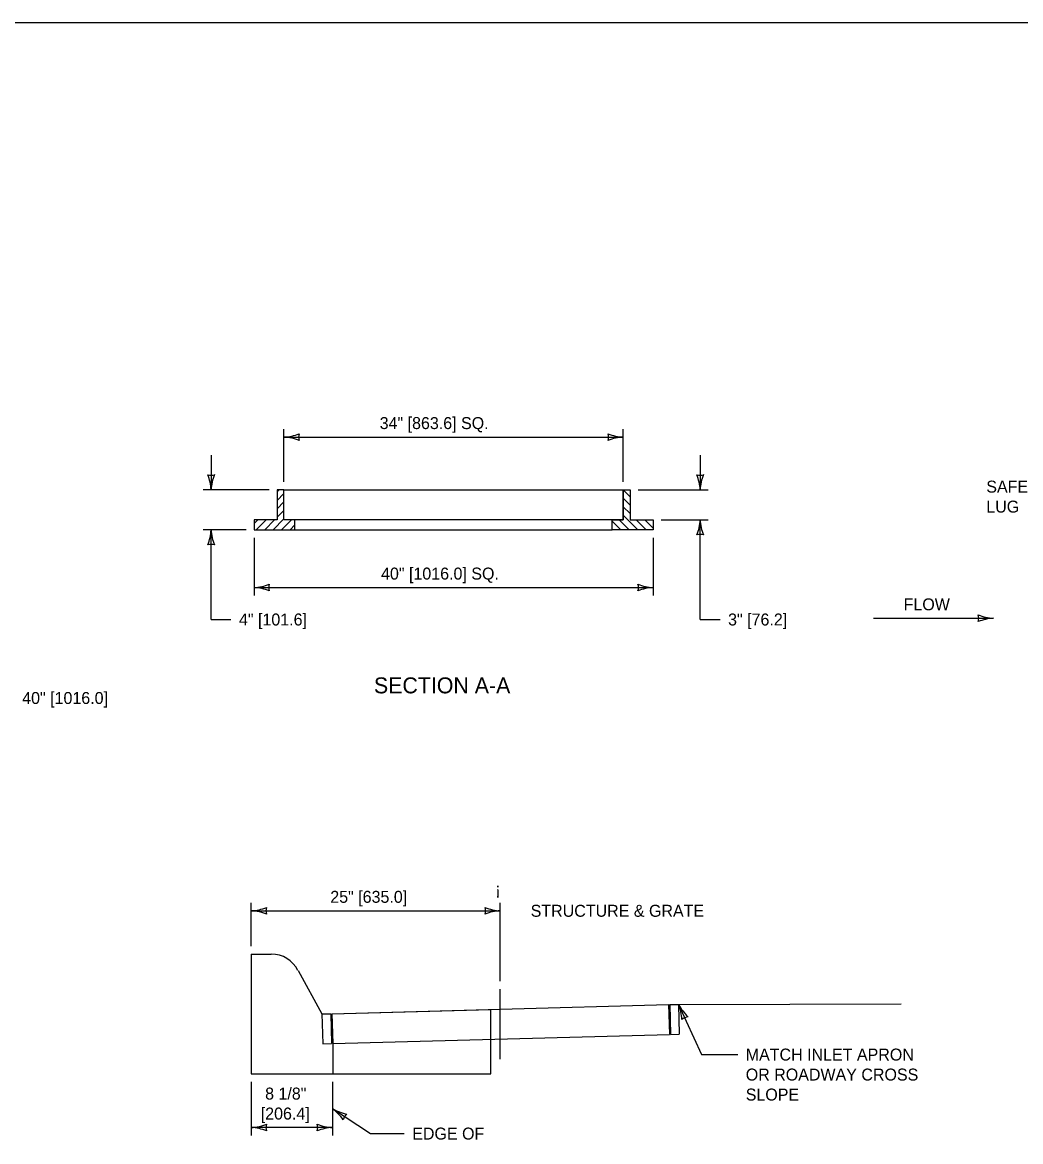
# Model space of a CAD drawing. Extents: x 49991.4 to 50041.6, y 49987.6 to 50011.4.
# Drawn here: x 50003.39 to 50008.39, y 49993.39 to 49999 of the extents above; entities that cross this region are included whole.
import ezdxf

# ---------------------------------------------------------------- set-up
doc = ezdxf.new("R2010")
doc.units = 0
for name, color, linetype in [('Level 1', 7, 'Continuous'), ('Level 2', 7, 'Continuous'), ('Level 3', 7, 'Continuous'), ('Level 5', 7, 'Continuous')]:
    doc.layers.add(name, color=color, linetype=linetype)

msp = doc.modelspace()

# ---------------------------------------------------------------- linework, layer by layer
at = {"layer": 'Level 1'}
for p, q in [((50004.7022, 49996.6557), (50004.6678, 49996.6557)), ((50004.6678, 49996.6557), (50004.6678, 49996.5057)), ((50004.6678, 49996.6453), (50004.6783, 49996.6557)), ((50004.7022, 49996.5057), (50004.7022, 49996.6557)), ((50006.4022, 49996.5057), (50006.4022, 49996.6557)), ((50006.4022, 49996.6557), (50006.4366, 49996.6557)), ((50006.4023, 49996.6557), (50006.4366, 49996.6214)), ((50006.4366, 49996.6557), (50006.4366, 49996.5057)), ((50004.6678, 49996.6029), (50004.7022, 49996.6373)), ((50004.6678, 49996.5604), (50004.7022, 49996.5948)), ((50006.4022, 49996.6134), (50006.4366, 49996.579)), ((50004.6678, 49996.518), (50004.7022, 49996.5524)), ((50006.4022, 49996.5709), (50006.4366, 49996.5366)), ((50006.4022, 49996.5285), (50006.475, 49996.4557)), ((50004.6678, 49996.5057), (50004.5522, 49996.5057)), ((50004.5522, 49996.5057), (50004.5522, 49996.4557)), ((50004.5522, 49996.4873), (50004.5707, 49996.5057)), ((50004.5631, 49996.4557), (50004.6131, 49996.5057)), ((50004.6055, 49996.4557), (50004.6555, 49996.5057)), ((50004.648, 49996.4557), (50004.7022, 49996.51)), ((50004.6904, 49996.4557), (50004.7404, 49996.5057)), ((50004.7569, 49996.5057), (50004.7022, 49996.5057)), ((50004.7328, 49996.4557), (50004.7569, 49996.4798)), ((50004.7569, 49996.4557), (50004.7569, 49996.5057)), ((50006.3475, 49996.4557), (50006.3475, 49996.5057)), ((50006.3475, 49996.4557), (50006.3475, 49996.5057)), ((50006.3475, 49996.5057), (50006.4022, 49996.5057)), ((50006.3475, 49996.4983), (50006.3902, 49996.4557)), ((50006.3826, 49996.5057), (50006.4326, 49996.4557)), ((50006.4366, 49996.5057), (50006.5522, 49996.5057)), ((50006.4674, 49996.5057), (50006.5174, 49996.4557)), ((50006.5099, 49996.5057), (50006.5522, 49996.4634)), ((50006.5522, 49996.5057), (50006.5522, 49996.4557)), ((50004.5522, 49996.4557), (50004.7569, 49996.4557)), ((50004.7569, 49996.4557), (50006.3475, 49996.4557)), ((50006.3475, 49996.4559), (50006.3477, 49996.4557)), ((50006.5522, 49996.4557), (50006.3475, 49996.4557)), ((50004.5386, 49994.3283), (50004.6386, 49994.3283)), ((50004.5386, 49994.3283), (50004.5386, 49993.7283)), ((50004.7725, 49994.246), (50004.8927, 49994.0283)), ((50004.9426, 49994.0296), (50006.6295, 49994.0748)), ((50006.6295, 49994.0748), (50006.6335, 49993.9249)), ((50006.6358, 49994.075), (50006.6795, 49994.0762)), ((50006.6358, 49994.075), (50006.6398, 49993.925)), ((50006.6795, 49994.0762), (50007.7957, 49994.0782)), ((50006.6795, 49994.0762), (50006.6835, 49993.9262)), ((50004.8927, 49994.0283), (50004.9364, 49994.0294)), ((50004.8927, 49994.0283), (50004.9364, 49994.0294)), ((50004.8927, 49994.0283), (50004.8967, 49993.8783)), ((50004.9364, 49994.0294), (50004.9404, 49993.8795)), ((50004.9426, 49994.0296), (50005.7386, 49994.0509)), ((50004.9426, 49994.0296), (50004.9467, 49993.8797)), ((50005.7386, 49993.7283), (50005.7386, 49994.0509)), ((50004.9467, 49993.8797), (50006.6335, 49993.9249)), ((50006.6398, 49993.925), (50006.6835, 49993.9262)), ((50004.8967, 49993.8783), (50004.9404, 49993.8795)), ((50004.9467, 49993.8797), (50004.9467, 49993.7283)), ((50004.5386, 49993.7283), (50005.7386, 49993.7283))]:
    msp.add_line(p, q, dxfattribs=at)
for points in [[(49999.3835, 49998.9992), (50016.7501, 49998.9992), (50016.7501, 49987.7988), (49999.3835, 49987.7988)], [(50006.4022, 49996.5057), (50004.7022, 49996.5057), (50004.7022, 49996.6557), (50006.4022, 49996.6557)]]:
    msp.add_lwpolyline(points, close=True, dxfattribs=at)
msp.add_arc((50004.6386, 49994.1783), 0.15, 26.8267, 90, dxfattribs=at)
at = {"layer": 'Level 3'}
for p, q in [((50004.7022, 49996.6957), (50004.7022, 49996.9604)), ((50004.7022, 49996.9204), (50006.4022, 49996.9204)), ((50006.4022, 49996.6957), (50006.4022, 49996.9604)), ((50004.3367, 49996.8292), (50004.3367, 49996.6557)), ((50006.788, 49996.8292), (50006.788, 49996.6557)), ((50004.6278, 49996.6557), (50004.2967, 49996.6557)), ((50006.4766, 49996.6557), (50006.828, 49996.6557)), ((50006.5922, 49996.5057), (50006.828, 49996.5057)), ((50006.788, 49996.0057), (50006.788, 49996.5057)), ((50004.5122, 49996.4557), (50004.2967, 49996.4557)), ((50004.3367, 49996.0057), (50004.3367, 49996.4557)), ((50004.5522, 49996.4157), (50004.5522, 49996.1259)), ((50006.5522, 49996.4157), (50006.5522, 49996.1259)), ((50004.5522, 49996.1659), (50006.5522, 49996.1659)), ((50004.3367, 49996.0057), (50004.4367, 49996.0057)), ((50006.788, 49996.0057), (50006.888, 49996.0057)), ((50007.6575, 49996.0117), (50008.2575, 49996.0117)), ((50004.5386, 49994.3683), (50004.5386, 49994.5854)), ((50005.7861, 49994.1922), (50005.7861, 49994.5854)), ((50004.5386, 49994.5454), (50005.7861, 49994.5454)), ((50006.6802, 49994.0762), (50006.7952, 49993.8246)), ((50006.7952, 49993.8246), (50006.9764, 49993.8246)), ((50004.5386, 49993.6883), (50004.5386, 49993.4189)), ((50004.9449, 49993.6883), (50004.9449, 49993.4189)), ((50004.9449, 49993.5536), (50005.1365, 49993.4285)), ((50004.9449, 49993.4589), (50004.5386, 49993.4589)), ((50005.1365, 49993.4285), (50005.305, 49993.4285))]:
    msp.add_line(p, q, dxfattribs=at)
for centre, radius, start, end in [((50004.6907, 49997.1531), 0.233, 272.8273, 292.0772), ((50004.6931, 49996.6983), 0.2223, 67.456, 87.6395), ((50004.8304, 49996.9204), 0.0548, 162.1388, 197.8612), ((50006.4114, 49997.1425), 0.2223, 247.456, 267.6395), ((50006.274, 49996.9204), 0.0548, 342.1388, 17.8612), ((50006.4137, 49996.6877), 0.233, 92.8273, 112.0772), ((50004.3367, 49996.7839), 0.0548, 252.1388, 287.8612), ((50004.104, 49996.6442), 0.233, 2.8273, 22.0772), ((50004.5589, 49996.6466), 0.2223, 157.456, 177.6395), ((50006.788, 49996.7839), 0.0548, 252.1388, 287.8612), ((50006.5552, 49996.6442), 0.233, 2.8273, 22.0772), ((50007.0101, 49996.6466), 0.2223, 157.456, 177.6395), ((50006.5658, 49996.5149), 0.2223, 337.456, 357.6395), ((50007.0207, 49996.5172), 0.233, 182.8273, 202.0772), ((50004.1146, 49996.4649), 0.2223, 337.456, 357.6395), ((50004.5695, 49996.4672), 0.233, 182.8273, 202.0772), ((50006.788, 49996.3775), 0.0548, 72.1388, 107.8612), ((50004.3367, 49996.3275), 0.0548, 72.1388, 107.8612), ((50004.5407, 49996.3987), 0.233, 272.8273, 292.0772), ((50004.5431, 49995.9438), 0.2223, 67.456, 87.6395), ((50004.6804, 49996.1659), 0.0548, 162.1388, 197.8612), ((50006.5614, 49996.3881), 0.2223, 247.456, 267.6395), ((50006.424, 49996.1659), 0.0548, 342.1388, 17.8612), ((50006.5637, 49995.9332), 0.233, 92.8273, 112.0772), ((50008.2667, 49996.2339), 0.2223, 247.456, 267.6395), ((50008.1293, 49996.0117), 0.0548, 342.1388, 17.8612), ((50008.269, 49995.779), 0.233, 92.8273, 112.0772), ((50004.5271, 49994.7781), 0.233, 272.8273, 292.0772), ((50004.5295, 49994.3233), 0.2223, 67.456, 87.6395), ((50004.6668, 49994.5454), 0.0548, 162.1388, 197.8612), ((50005.7952, 49994.7675), 0.2223, 247.456, 267.6395), ((50005.6579, 49994.5454), 0.0548, 342.1388, 17.8612), ((50005.7976, 49994.3127), 0.233, 92.8273, 112.0772), ((50006.4743, 49993.9921), 0.2223, 2.0239, 22.2074), ((50006.887, 49994.1834), 0.233, 207.3952, 226.645), ((50006.7335, 49993.9596), 0.0548, 96.7067, 132.4291), ((50004.8157, 49993.3726), 0.2223, 34.309, 54.4925), ((50005.0625, 49993.7547), 0.233, 239.6803, 258.9302), ((50005.0522, 49993.4835), 0.0548, 128.9918, 164.7142), ((50004.5271, 49993.6916), 0.233, 272.8273, 292.0772), ((50004.5295, 49993.2367), 0.2223, 67.456, 87.6395), ((50004.6668, 49993.4589), 0.0548, 162.1388, 197.8612), ((50004.954, 49993.681), 0.2223, 247.456, 267.6395), ((50004.8166, 49993.4589), 0.0548, 342.1388, 17.8612), ((50004.9564, 49993.2262), 0.233, 92.8273, 112.0772)]:
    msp.add_arc(centre, radius, start, end, dxfattribs=at)
at = {"layer": 'Level 5'}
msp.add_line((50005.7861, 49993.8022), (50005.7861, 49994.1522), dxfattribs=at)

# ---------------------------------------------------------------- texts
at = {"layer": 'Level 2'}
for s, height, p in [('34" [863.6] SQ.', 0.06, (50005.1819, 49996.9604)), ('SAFETY', 0.06, (50008.2221, 49996.6418)), ('LUG', 0.06, (50008.2221, 49996.5416)), ('40" [1016.0] SQ.', 0.06, (50005.1888, 49996.2059)), ('FLOW', 0.06, (50007.8077, 49996.0517)), ('4" [101.6]', 0.06, (50004.4767, 49995.9757)), ('3" [76.2]', 0.06, (50006.928, 49995.9757)), ('SECTION A-A', 0.08, (50005.1531, 49995.6355)), ('40" [1016.0]', 0.06, (50003.3903, 49995.5822)), ('25" [635.0]', 0.06, (50004.9343, 49994.5854)), ('¡', 0.06, (50005.761, 49994.6254)), ('STRUCTURE & GRATE', 0.06, (50005.9386, 49994.5154)), ('MATCH INLET APRON ', 0.06, (50007.0164, 49993.7946)), ('OR ROADWAY CROSS', 0.06, (50007.0164, 49993.6944)), ('8 1/8"', 0.06, (50004.6077, 49993.5991)), ('SLOPE', 0.06, (50007.0164, 49993.5942)), ('[206.4]', 0.06, (50004.5858, 49993.4989)), ('EDGE OF', 0.06, (50005.345, 49993.3985))]:
    msp.add_text(s, height=height, dxfattribs=at).set_placement(p)

doc.saveas('drawing.dxf')
